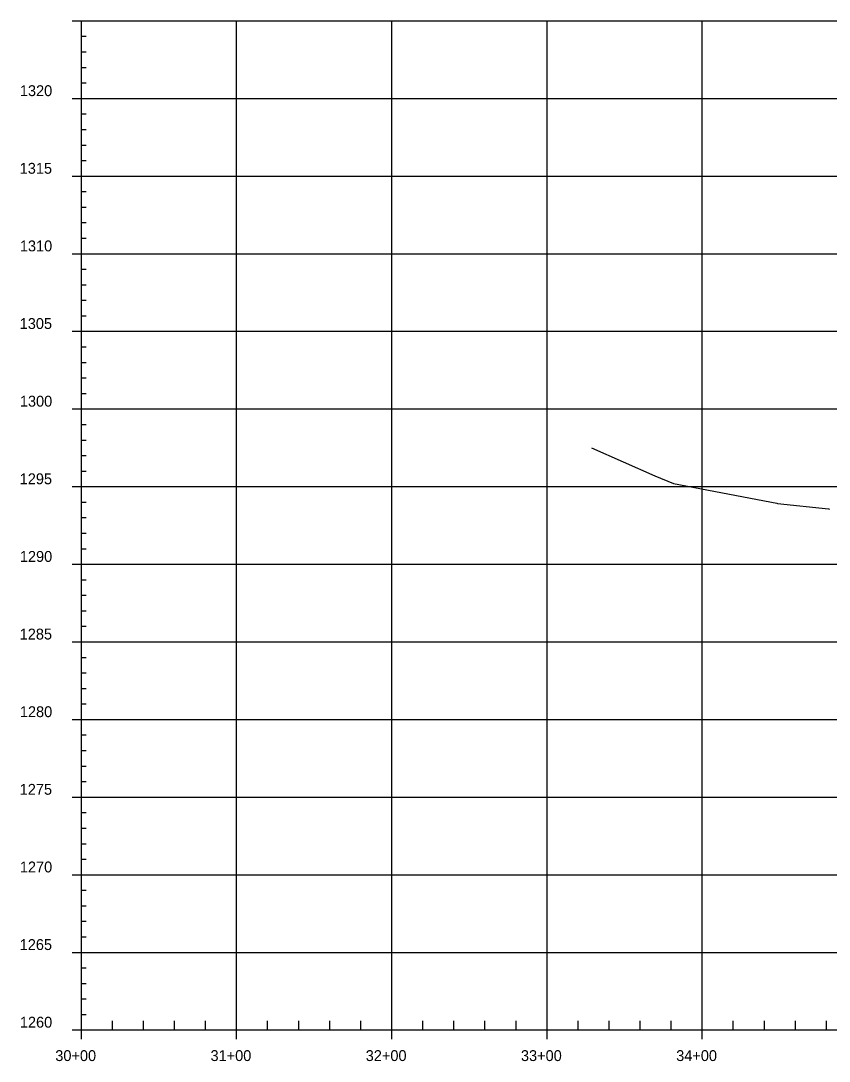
# Model space of a CAD drawing. Extents: x 670877 to 686811, y 705985 to 708501.
# Drawn here: x 684434 to 684955, y 707018 to 707688 of the extents above; entities that cross this region are included whole.
import ezdxf

# ---------------------------------------------------------------- set-up
doc = ezdxf.new("R2010")
doc.units = 0
for name, color, linetype in [('30', 7, 'Continuous'), ('37', 7, 'Continuous'), ('R_Drainage LEFT', 7, 'Continuous'), ('R_Drainage RIGHT', 7, 'Continuous'), ('R_Exist Surface', 7, 'Continuous')]:
    doc.layers.add(name, color=color, linetype=linetype)

msp = doc.modelspace()

# ---------------------------------------------------------------- linework, layer by layer
at = {"layer": '37'}
for p, q in [((684467.03, 707688.43), (684473.03, 707688.43)), ((684473.03, 707038.43), (684473.03, 707688.43)), ((684473.03, 707688.43), (686573.03, 707688.43)), ((684573.03, 707038.43), (684573.03, 707688.43)), ((684673.03, 707038.43), (684673.03, 707688.43)), ((684773.03, 707038.43), (684773.03, 707688.43)), ((684873.03, 707038.43), (684873.03, 707688.43)), ((684473.03, 707678.43), (684476.03, 707678.43)), ((684473.03, 707668.43), (684476.03, 707668.43)), ((684473.03, 707658.43), (684476.03, 707658.43)), ((684473.03, 707648.43), (684476.03, 707648.43)), ((684467.03, 707638.43), (684473.03, 707638.43)), ((684473.03, 707638.43), (686573.03, 707638.43)), ((684473.03, 707628.43), (684476.03, 707628.43)), ((684473.03, 707618.43), (684476.03, 707618.43)), ((684473.03, 707608.43), (684476.03, 707608.43)), ((684473.03, 707598.43), (684476.03, 707598.43)), ((684467.03, 707588.43), (684473.03, 707588.43)), ((684473.03, 707588.43), (686573.03, 707588.43)), ((684473.03, 707578.43), (684476.03, 707578.43)), ((684473.03, 707568.43), (684476.03, 707568.43)), ((684473.03, 707558.43), (684476.03, 707558.43)), ((684473.03, 707548.43), (684476.03, 707548.43)), ((684467.03, 707538.43), (684473.03, 707538.43)), ((684473.03, 707538.43), (686573.03, 707538.43)), ((684473.03, 707528.43), (684476.03, 707528.43)), ((684473.03, 707518.43), (684476.03, 707518.43)), ((684473.03, 707508.43), (684476.03, 707508.43)), ((684473.03, 707498.43), (684476.03, 707498.43)), ((684467.03, 707488.43), (684473.03, 707488.43)), ((684473.03, 707488.43), (686573.03, 707488.43)), ((684473.03, 707478.43), (684476.03, 707478.43)), ((684473.03, 707468.43), (684476.03, 707468.43)), ((684473.03, 707458.43), (684476.03, 707458.43)), ((684473.03, 707448.43), (684476.03, 707448.43)), ((684467.03, 707438.43), (684473.03, 707438.43)), ((684473.03, 707438.43), (686573.03, 707438.43)), ((684473.03, 707428.43), (684476.03, 707428.43)), ((684473.03, 707418.43), (684476.03, 707418.43)), ((684473.03, 707408.43), (684476.03, 707408.43)), ((684473.03, 707398.43), (684476.03, 707398.43)), ((684467.03, 707388.43), (684473.03, 707388.43)), ((684473.03, 707388.43), (686573.03, 707388.43)), ((684473.03, 707378.43), (684476.03, 707378.43)), ((684473.03, 707368.43), (684476.03, 707368.43)), ((684473.03, 707358.43), (684476.03, 707358.43)), ((684473.03, 707348.43), (684476.03, 707348.43)), ((684467.03, 707338.43), (684473.03, 707338.43)), ((684473.03, 707338.43), (686573.03, 707338.43)), ((684473.03, 707328.43), (684476.03, 707328.43)), ((684473.03, 707318.43), (684476.03, 707318.43)), ((684473.03, 707308.43), (684476.03, 707308.43)), ((684473.03, 707298.43), (684476.03, 707298.43)), ((684467.03, 707288.43), (684473.03, 707288.43)), ((684473.03, 707288.43), (686573.03, 707288.43)), ((684473.03, 707278.43), (684476.03, 707278.43)), ((684473.03, 707268.43), (684476.03, 707268.43)), ((684473.03, 707258.43), (684476.03, 707258.43)), ((684473.03, 707248.43), (684476.03, 707248.43)), ((684467.03, 707238.43), (684473.03, 707238.43)), ((684473.03, 707238.43), (686573.03, 707238.43)), ((684473.03, 707228.43), (684476.03, 707228.43)), ((684473.03, 707218.43), (684476.03, 707218.43)), ((684473.03, 707208.43), (684476.03, 707208.43)), ((684473.03, 707198.43), (684476.03, 707198.43)), ((684467.03, 707188.43), (684473.03, 707188.43)), ((684473.03, 707188.43), (686573.03, 707188.43)), ((684473.03, 707178.43), (684476.03, 707178.43)), ((684473.03, 707168.43), (684476.03, 707168.43)), ((684473.03, 707158.43), (684476.03, 707158.43)), ((684473.03, 707148.43), (684476.03, 707148.43)), ((684467.03, 707138.43), (684473.03, 707138.43)), ((684473.03, 707138.43), (686573.03, 707138.43)), ((684473.03, 707128.43), (684476.03, 707128.43)), ((684473.03, 707118.43), (684476.03, 707118.43)), ((684473.03, 707108.43), (684476.03, 707108.43)), ((684473.03, 707098.43), (684476.03, 707098.43)), ((684467.03, 707088.43), (684473.03, 707088.43)), ((684473.03, 707088.43), (686573.03, 707088.43)), ((684473.03, 707078.43), (684476.03, 707078.43)), ((684473.03, 707068.43), (684476.03, 707068.43)), ((684473.03, 707058.43), (684476.03, 707058.43)), ((684473.03, 707048.43), (684476.03, 707048.43)), ((684493.03, 707038.43), (684493.03, 707044.43)), ((684513.03, 707038.43), (684513.03, 707044.43)), ((684533.03, 707038.43), (684533.03, 707044.43)), ((684553.03, 707038.43), (684553.03, 707044.43)), ((684593.03, 707038.43), (684593.03, 707044.43)), ((684613.03, 707038.43), (684613.03, 707044.43)), ((684633.03, 707038.43), (684633.03, 707044.43)), ((684653.03, 707038.43), (684653.03, 707044.43)), ((684693.03, 707038.43), (684693.03, 707044.43)), ((684713.03, 707038.43), (684713.03, 707044.43)), ((684733.03, 707038.43), (684733.03, 707044.43)), ((684753.03, 707038.43), (684753.03, 707044.43)), ((684793.03, 707038.43), (684793.03, 707044.43)), ((684813.03, 707038.43), (684813.03, 707044.43)), ((684833.03, 707038.43), (684833.03, 707044.43)), ((684853.03, 707038.43), (684853.03, 707044.43)), ((684893.03, 707038.43), (684893.03, 707044.43)), ((684913.03, 707038.43), (684913.03, 707044.43)), ((684933.03, 707038.43), (684933.03, 707044.43)), ((684953.03, 707038.43), (684953.03, 707044.43)), ((684467.03, 707038.43), (684473.03, 707038.43)), ((684473.03, 707038.43), (686573.03, 707038.43)), ((684473.03, 707032.43), (684473.03, 707038.43)), ((684573.03, 707032.43), (684573.03, 707038.43)), ((684673.03, 707032.43), (684673.03, 707038.43)), ((684773.03, 707032.43), (684773.03, 707038.43)), ((684873.03, 707032.43), (684873.03, 707038.43))]:
    msp.add_line(p, q, dxfattribs=at)
at = {"layer": 'R_Exist Surface'}
msp.add_lwpolyline([(684801.72, 707413.36), (684842.47, 707395.44), (684854.45, 707390.34), (684921.17, 707377.67), (684921.54, 707377.64), (684954.35, 707374.02), (684954.94, 707373.95)], dxfattribs=at)

# ---------------------------------------------------------------- texts
at = {"layer": '30'}
for s, p in [('1320', (684433.41, 707639.93)), ('1315', (684433.29, 707589.93)), ('1310', (684433.41, 707539.93)), ('1305', (684433.29, 707489.93)), ('1300', (684433.41, 707439.93)), ('1295', (684433.29, 707389.93)), ('1290', (684433.41, 707339.93)), ('1285', (684433.29, 707289.93)), ('1280', (684433.41, 707239.93)), ('1275', (684433.29, 707189.93)), ('1270', (684433.41, 707139.93)), ('1265', (684433.29, 707089.93)), ('1260', (684433.41, 707039.93)), ('30+00', (684456.22, 707018.43)), ('31+00', (684556.22, 707018.43)), ('32+00', (684656.22, 707018.43)), ('33+00', (684756.22, 707018.43)), ('34+00', (684856.22, 707018.43))]:
    msp.add_text(s, height=7, dxfattribs=at).set_placement(p)
at = {"layer": 'R_Drainage LEFT'}
msp.add_text('-', height=0.0001, dxfattribs=at).set_placement((684473.03, 707038.43))
at = {"layer": 'R_Drainage RIGHT'}
msp.add_text('-', height=0.0001, dxfattribs=at).set_placement((684473.03, 707038.43))

doc.saveas('drawing.dxf')
